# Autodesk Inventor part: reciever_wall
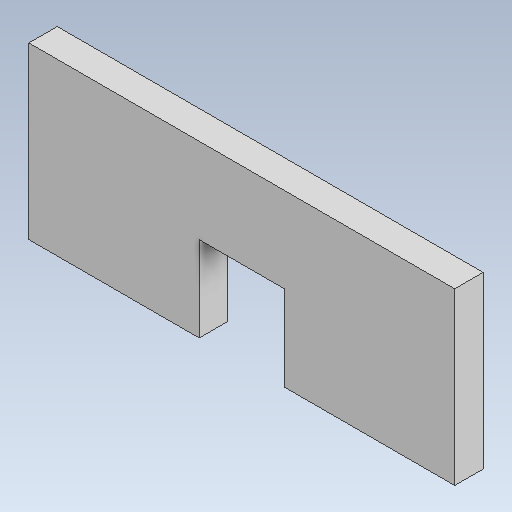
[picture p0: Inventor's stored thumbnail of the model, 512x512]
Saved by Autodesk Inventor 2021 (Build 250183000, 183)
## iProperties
Created: 2026-10
Part Number: reciever_wall
Material: Generic
Document SubType Name: Modeling
Designer: alolo
Density: 1 g/cm^3
Appearance: Default
Author: alolo
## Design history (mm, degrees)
sketch "Sketch1"
  geometry: L1 (0, 0)-(75, 0); L2 (75, 0)-(75, 30); L3 (75, 30)-(0, 30); L4 (0, 30)-(0, 0); L5 (30, 0)-(45, 0); L6 (45, 0)-(45, 15); L7 (45, 15)-(30, 15); L8 (30, 15)-(30, 0); 4 further points
  constraints: 16 end point, 4 parallel, 2 horizontal, 2 midpoint, 2 perpendicular, 1 coincident, 1 point on line, 1 vertical alignment
  dimensions: "d0" = 75 distance of L3.end L2.end; "d1" = 30 distance of L3.end L1.start; "d2" = 15 distance of L7.end L6.end; "d3" = 15 distance of L6.end L5.end
extrude "Extrusion1" new body sketch "Sketch1" distance "d4" = 5 (= wood_thickness); taper "d5" = 0 deg
body "Solid1"
other parameters: "slide_length" = 195 [user parameter], "slide_angle" = 7 deg [user parameter], "slide_width" = 65 [user parameter], "wood_thickness" = 5 [user parameter; used in 1 equation term], "aclyric_thickness" = 6 [user parameter]
